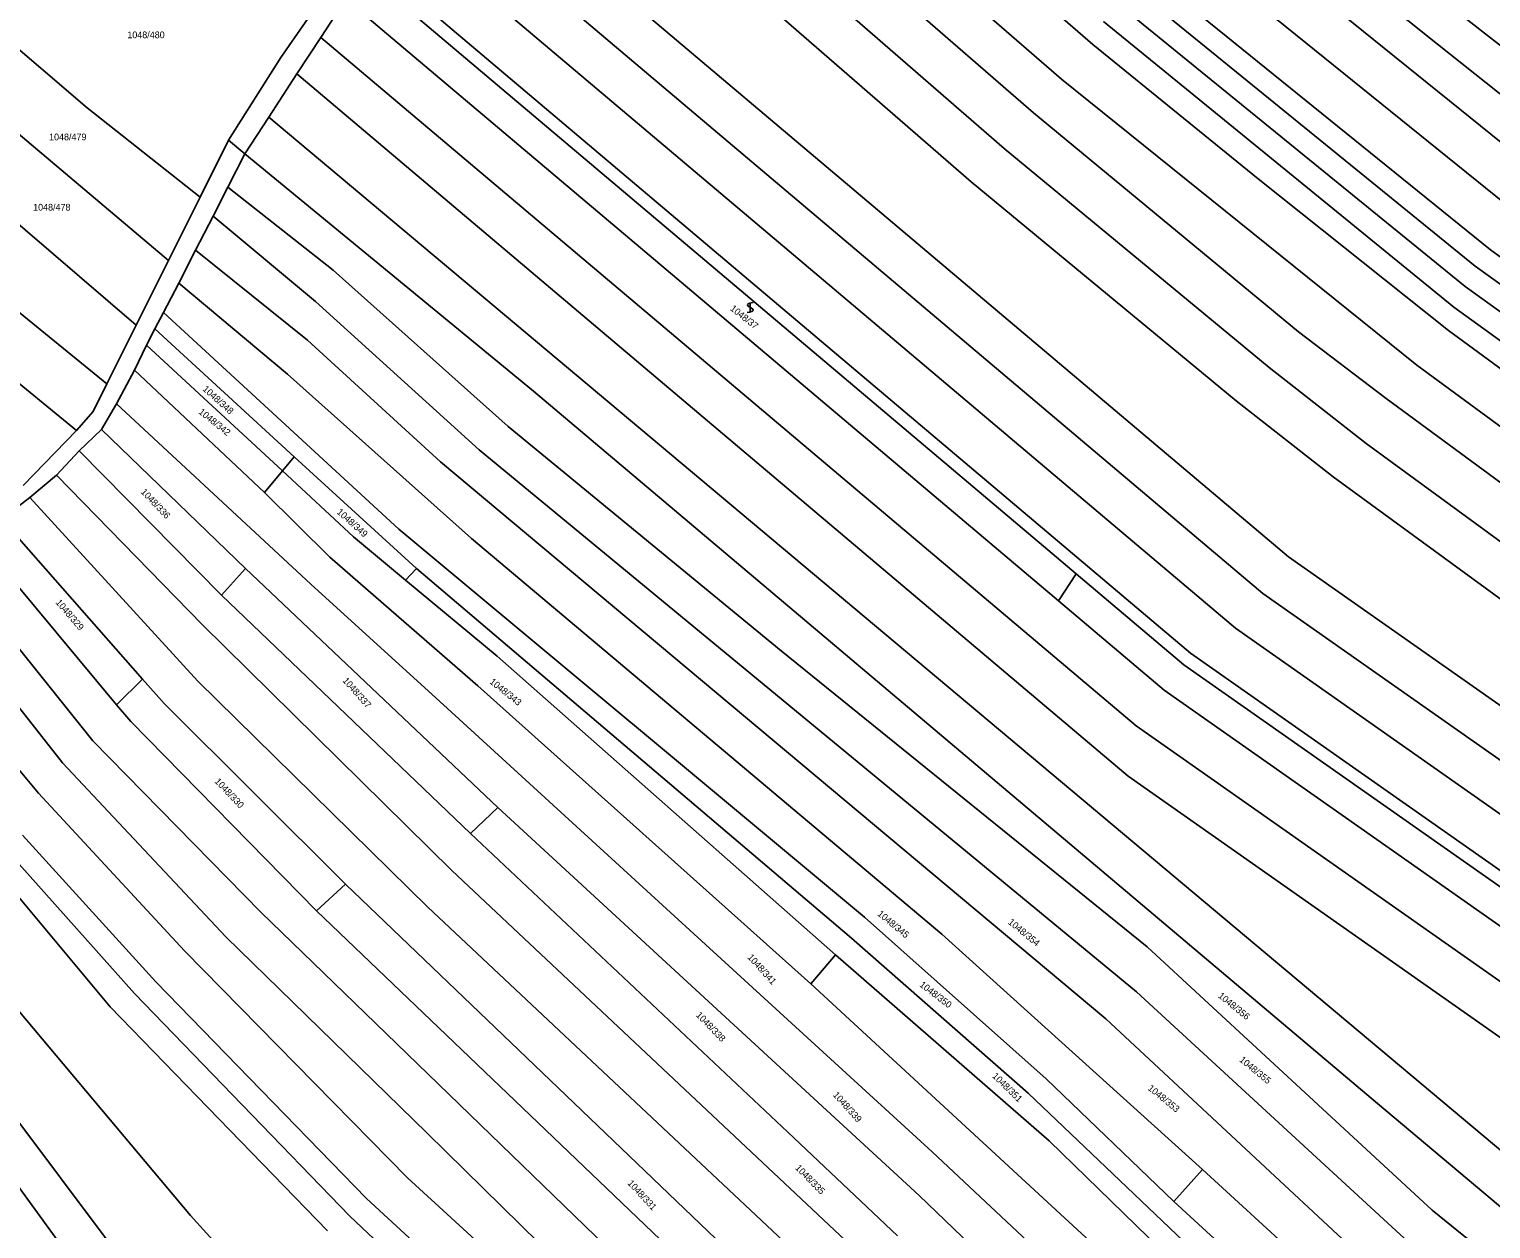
# Model space of a CAD drawing. Extents: x -580630 to -576196, y -1189024 to -1183567.
# Drawn here: x -577874.8 to -577503.7, y -1186079.1 to -1185774.5 of the extents above; entities that cross this region are included whole.
import ezdxf

# ---------------------------------------------------------------- set-up
doc = ezdxf.new("R2010")
doc.units = 0
for name, color, linetype in [('Vrstva 1', 7, 'Continuous'), ('Vrstva 18', 7, 'Continuous'), ('Vrstva 25', 7, 'Continuous'), ('Vrstva 6', 7, 'Continuous')]:
    doc.layers.add(name, color=color, linetype=linetype)

msp = doc.modelspace()

# ---------------------------------------------------------------- linework, layer by layer
at = {"layer": 'Vrstva 1'}
for p, q in [((-577664.3, -1185651.28), (-577332.73, -1185910.23)), ((-577732.43, -1185697.77), (-577619.85, -1185795.71)), ((-577627.3, -1185804.73), (-577740.7, -1185706.11)), ((-577749.09, -1185714.58), (-577635.66, -1185813.22)), ((-577677.91, -1185714.69), (-577604.76, -1185778.38)), ((-577612.74, -1185787.19), (-577685.89, -1185723.49)), ((-577662.14, -1185818.03), (-577765.26, -1185730.91)), ((-577773.22, -1185738.94), (-577670.09, -1185826.06)), ((-577578.38, -1185740.84), (-577487.79, -1185814.01)), ((-577781.14, -1185746.94), (-577678.01, -1185834.06)), ((-577494.62, -1185823.18), (-577585.21, -1185750.01)), ((-577551.27, -1185751.07), (-577517.23, -1185778.28)), ((-577683.41, -1185845.46), (-577786.54, -1185758.34)), ((-577704.33, -1185832.19), (-577788.36, -1185761.2)), ((-577507.7, -1185834.65), (-577596.7, -1185762.21)), ((-577503.8, -1185830.52), (-577591.91, -1185759.17)), ((-577800.75, -1185776.53), (-577794.39, -1185766.77)), ((-577794.39, -1185766.77), (-577710.36, -1185837.76)), ((-577599.25, -1185767.38), (-577510.25, -1185839.82)), ((-577810.89, -1185781.66), (-577802.62, -1185769.68)), ((-577513.13, -1185845.04), (-577602.04, -1185772.49)), ((-577806.8, -1185785.82), (-577800.75, -1185776.53)), ((-577697.62, -1185863.65), (-577800.75, -1185776.53)), ((-577604.76, -1185778.38), (-577562.76, -1185812.47)), ((-577517.23, -1185778.28), (-577477.78, -1185809.68)), ((-577824.19, -1185802.68), (-577810.89, -1185781.66)), ((-577813.91, -1185796.76), (-577806.8, -1185785.82)), ((-577806.8, -1185785.82), (-577703.68, -1185872.95)), ((-577522.47, -1185859.77), (-577612.74, -1185787.19)), ((-577820.01, -1185806.11), (-577813.91, -1185796.76)), ((-577699.01, -1185893.18), (-577813.91, -1185796.76)), ((-577619.85, -1185795.71), (-577552.56, -1185851.31)), ((-577831.37, -1185817.08), (-577824.19, -1185802.68)), ((-577820.01, -1185806.11), (-577824.19, -1185802.68)), ((-577824.35, -1185814.6), (-577820.01, -1185806.11)), ((-577820.01, -1185806.11), (-577746.74, -1185866.34)), ((-577559.97, -1185860.36), (-577627.3, -1185804.73)), ((-577635.66, -1185813.22), (-577568.33, -1185868.86)), ((-577562.76, -1185812.47), (-577514.49, -1185850.96)), ((-577839.43, -1185833.23), (-577831.37, -1185817.08)), ((-577828.11, -1185821.96), (-577824.35, -1185814.6)), ((-577555.11, -1185908.44), (-577662.14, -1185818.03)), ((-577832.52, -1185830.58), (-577828.11, -1185821.96)), ((-577670.09, -1185826.06), (-577561.55, -1185917.75)), ((-577836.81, -1185838.97), (-577832.52, -1185830.58)), ((-577616.14, -1185906.69), (-577704.33, -1185832.19)), ((-577412.08, -1185897.16), (-577503.8, -1185830.52)), ((-577847.6, -1185849.62), (-577839.43, -1185833.23)), ((-577678.01, -1185834.06), (-577568.51, -1185926.57)), ((-577415.03, -1185901.48), (-577507.7, -1185834.65)), ((-577840.66, -1185846.38), (-577836.81, -1185838.97)), ((-577710.36, -1185837.76), (-577613.45, -1185919.63)), ((-577510.25, -1185839.82), (-577417.58, -1185906.64)), ((-577842.84, -1185850.56), (-577840.66, -1185846.38)), ((-577579.93, -1185932.89), (-577683.41, -1185845.46)), ((-577420.56, -1185911.96), (-577513.13, -1185845.04)), ((-577855.03, -1185864.52), (-577847.6, -1185849.62)), ((-577845, -1185854.71), (-577842.84, -1185850.56)), ((-577514.49, -1185850.96), (-577440.82, -1185905.19)), ((-577848, -1185861.04), (-577845, -1185854.71)), ((-577552.56, -1185851.31), (-577530.26, -1185868.26)), ((-577852.6, -1185869.56), (-577848, -1185861.04)), ((-577535.34, -1185879.64), (-577559.97, -1185860.36)), ((-577448.81, -1185913.99), (-577522.47, -1185859.77)), ((-577858.52, -1185871.5), (-577855.03, -1185864.52)), ((-577593.78, -1185951.38), (-577697.62, -1185863.65)), ((-577856.45, -1185876.12), (-577852.6, -1185869.56)), ((-577746.74, -1185866.34), (-577532.48, -1186047.27)), ((-577568.33, -1185868.86), (-577543.7, -1185888.14)), ((-577530.26, -1185868.26), (-577456.78, -1185922.41)), ((-577862.79, -1185876.35), (-577858.52, -1185871.5)), ((-577703.68, -1185872.95), (-577595.78, -1185964.13)), ((-577876.32, -1185890.37), (-577862.79, -1185876.35)), ((-577856.45, -1185876.12), (-577862.11, -1185881.51)), ((-577462.45, -1185933.01), (-577535.34, -1185879.64)), ((-577867.84, -1185887.69), (-577862.11, -1185881.51)), ((-577874.61, -1185893.34), (-577867.84, -1185887.69)), ((-577543.7, -1185888.14), (-577470.8, -1185941.51)), ((-577881.68, -1185898.84), (-577874.61, -1185893.34)), ((-577584.11, -1185989.6), (-577699.01, -1185893.18)), ((-577609, -1185912.72), (-577616.14, -1185906.69)), ((-577410.98, -1186009.73), (-577555.11, -1185908.44)), ((-577613.45, -1185919.63), (-577609, -1185912.72)), ((-577581.64, -1185935.83), (-577609, -1185912.72)), ((-577561.55, -1185917.75), (-577417.41, -1186019.03)), ((-577613.45, -1185919.63), (-577586.61, -1185942.3)), ((-577568.51, -1185926.57), (-577424.38, -1186027.85)), ((-577437.5, -1186037.11), (-577581.64, -1185935.83)), ((-577435.79, -1186034.17), (-577579.93, -1185932.89)), ((-577586.61, -1185942.3), (-577442.47, -1186043.59)), ((-577449.64, -1186052.66), (-577593.78, -1185951.38)), ((-577595.78, -1185964.13), (-577451.64, -1186065.41)), ((-577474.77, -1186081.35), (-577584.11, -1185989.6)), ((-577532.48, -1186047.27), (-577480.98, -1186090.61))]:
    msp.add_line(p, q, dxfattribs=at)
at = {"layer": 'Vrstva 25'}
for points in [[(-577690.97, -1185843.89), (-577691.48, -1185843.95), (-577691.83, -1185844), (-577692.07, -1185844.08), (-577692.25, -1185844.19), (-577692.37, -1185844.28), (-577692.42, -1185844.45), (-577692.37, -1185844.68), (-577691.98, -1185845), (-577691.42, -1185845.31), (-577691.07, -1185845.58), (-577691, -1185845.78), (-577691.07, -1185845.98), (-577691.23, -1185846.11), (-577691.42, -1185846.18), (-577691.95, -1185846.31), (-577692.47, -1185846.38)], [(-577691.72, -1185846.39), (-577691.72, -1185845.12), (-577691.72, -1185843.89)]]:
    msp.add_lwpolyline(points, dxfattribs=at)
at = {"layer": 'Vrstva 6'}
for p, q in [((-577860.05, -1185794.41), (-577894.53, -1185764.98)), ((-577839.43, -1185833.23), (-577908.46, -1185774.88)), ((-577923.11, -1185784.8), (-577847.6, -1185849.62)), ((-577831.37, -1185817.08), (-577860.05, -1185794.41)), ((-577855.03, -1185864.52), (-577939.34, -1185795.85)), ((-577950.99, -1185804.05), (-577862.79, -1185876.35)), ((-577824.35, -1185814.6), (-577797.61, -1185835.65)), ((-577828.11, -1185821.96), (-577802.12, -1185843.61)), ((-577832.52, -1185830.58), (-577804.09, -1185853.45)), ((-577797.61, -1185835.65), (-577753.15, -1185875.32)), ((-577836.81, -1185838.97), (-577809.2, -1185862.03)), ((-577802.12, -1185843.61), (-577760.54, -1185881.29)), ((-577840.66, -1185846.38), (-577780.96, -1185901.39)), ((-577842.84, -1185850.56), (-577807.49, -1185883.08)), ((-577845, -1185854.71), (-577810.5, -1185886.6)), ((-577770.34, -1185884.35), (-577804.09, -1185853.45)), ((-577848, -1185861.04), (-577815.01, -1185892.1)), ((-577809.2, -1185862.03), (-577762.5, -1185903.79)), ((-577852.6, -1185869.56), (-577803.27, -1185915.37)), ((-577819.9, -1185911.43), (-577856.45, -1185876.12)), ((-577753.15, -1185875.32), (-577683.86, -1185932.3)), ((-577862.11, -1185881.51), (-577825.92, -1185918.14)), ((-577810.5, -1185886.6), (-577807.49, -1185883.08)), ((-577776.46, -1185911.38), (-577807.49, -1185883.08)), ((-577770.34, -1185884.35), (-577601.46, -1186025.8)), ((-577760.54, -1185881.29), (-577593.69, -1186018.87)), ((-577867.84, -1185887.69), (-577830.78, -1185925.68)), ((-577815.01, -1185892.1), (-577810.5, -1185886.6)), ((-577810.5, -1185886.6), (-577792.42, -1185903.4)), ((-577874.61, -1185893.34), (-577831.99, -1185940)), ((-577815.01, -1185892.1), (-577798.43, -1185908.53)), ((-577881.68, -1185898.84), (-577845.97, -1185939.54)), ((-577780.96, -1185901.39), (-577662.69, -1185999.97)), ((-577852.61, -1185946.01), (-577888.01, -1185903.5)), ((-577792.42, -1185903.4), (-577779.23, -1185914.36)), ((-577762.5, -1185903.79), (-577643.08, -1186004.26)), ((-577895.32, -1185909.32), (-577858.63, -1185955.13)), ((-577798.43, -1185908.53), (-577760.92, -1185941.24)), ((-577825.92, -1185918.14), (-577819.9, -1185911.43)), ((-577755.8, -1185972.07), (-577819.9, -1185911.43)), ((-577779.23, -1185914.36), (-577776.46, -1185911.38)), ((-577666.02, -1186005.31), (-577776.46, -1185911.38)), ((-577902.14, -1185915.36), (-577866.29, -1185960.73)), ((-577803.27, -1185915.37), (-577771.5, -1185944.23)), ((-577779.23, -1185914.36), (-577755.96, -1185933.7)), ((-577825.92, -1185918.14), (-577762.73, -1185978.7)), ((-577910.1, -1185923.35), (-577872.43, -1185968.42)), ((-577830.78, -1185925.68), (-577767.51, -1185988.09)), ((-577683.86, -1185932.3), (-577590.92, -1186007.5)), ((-577755.96, -1185933.7), (-577670.09, -1186009.52)), ((-577852.61, -1185946.01), (-577845.97, -1185939.54)), ((-577845.97, -1185939.54), (-577840.55, -1185945.72)), ((-577831.99, -1185940), (-577773.54, -1185997.43)), ((-577760.92, -1185941.24), (-577676.34, -1186016.85)), ((-577849, -1185950.23), (-577852.61, -1185946.01)), ((-577840.55, -1185945.72), (-577794.45, -1185991.55)), ((-577771.5, -1185944.23), (-577645.56, -1186059.56)), ((-577801.84, -1185998.32), (-577849, -1185950.23)), ((-577858.63, -1185955.13), (-577816, -1185998.7)), ((-577866.29, -1185960.73), (-577824.85, -1186004.91)), ((-577872.43, -1185968.42), (-577835.38, -1186008.52)), ((-577762.73, -1185978.7), (-577755.8, -1185972.07)), ((-577755.8, -1185972.07), (-577648.85, -1186070.58)), ((-577876.51, -1185979.11), (-577842.61, -1186016.34)), ((-577762.73, -1185978.7), (-577682.2, -1186054.57)), ((-577880.11, -1185983.34), (-577848.03, -1186019.36)), ((-577885.24, -1185985.52), (-577854.19, -1186022.75)), ((-577767.51, -1185988.09), (-577657.54, -1186091.42)), ((-577794.45, -1185991.55), (-577801.84, -1185998.32)), ((-577794.45, -1185991.55), (-577663.38, -1186117.12)), ((-577833.85, -1186075.71), (-577901.2, -1185995.5)), ((-577816, -1185998.7), (-577725.76, -1186085.99)), ((-577686.75, -1186108.38), (-577801.84, -1185998.32)), ((-577773.54, -1185997.43), (-577664.46, -1186099.81)), ((-577662.69, -1185999.97), (-577616.6, -1186040.97)), ((-577824.85, -1186004.91), (-577773.78, -1186054.8)), ((-577621.14, -1186044.67), (-577666.02, -1186005.31)), ((-577643.08, -1186004.26), (-577576.91, -1186064.03)), ((-577835.38, -1186008.52), (-577778.73, -1186066.11)), ((-577670.09, -1186009.52), (-577676.34, -1186016.85)), ((-577670.09, -1186009.52), (-577615.86, -1186056.7)), ((-577590.92, -1186007.5), (-577518.59, -1186074.31)), ((-577842.61, -1186016.34), (-577789.14, -1186071.36)), ((-577676.34, -1186016.85), (-577534.2, -1186147.99)), ((-577848.03, -1186019.36), (-577793.34, -1186075.89)), ((-577593.69, -1186018.87), (-577519.06, -1186087.55)), ((-577854.19, -1186022.75), (-577799.05, -1186079.58)), ((-577601.46, -1186025.8), (-577525.83, -1186096.16)), ((-577898.45, -1186039.68), (-577859.16, -1186093.53)), ((-577847.81, -1186091.45), (-577883.6, -1186043.78)), ((-577584.21, -1186072.18), (-577616.6, -1186040.97)), ((-577558.77, -1186104.07), (-577621.14, -1186044.67)), ((-577773.78, -1186054.8), (-577615.6, -1186209.77)), ((-577682.2, -1186054.57), (-577654.35, -1186080.86)), ((-577615.86, -1186056.7), (-577563.58, -1186107.51)), ((-577645.56, -1186059.56), (-577544.3, -1186154.15)), ((-577778.73, -1186066.11), (-577739.11, -1186102.44)), ((-577584.21, -1186072.18), (-577576.91, -1186064.03)), ((-577576.91, -1186064.03), (-577529.31, -1186107.59)), ((-577789.14, -1186071.36), (-577740.92, -1186115.71)), ((-577648.85, -1186070.58), (-577590.84, -1186126.36)), ((-577536.31, -1186115.98), (-577584.21, -1186072.18)), ((-577819.38, -1186091.56), (-577833.85, -1186075.71)), ((-577793.34, -1186075.89), (-577712.43, -1186151.86)), ((-577518.59, -1186074.31), (-577479.74, -1186105.8))]:
    msp.add_line(p, q, dxfattribs=at)

# ---------------------------------------------------------------- texts
at = {"layer": 'Vrstva 18'}
for s, p in [('1048/480', (-577849.86, -1185776.75)), ('1048/479', (-577869.726, -1185802.67)), ('1048/478', (-577873.776, -1185820.52))]:
    msp.add_text(s, height=1.7, dxfattribs=at).set_placement(p)
for s, rotation, p in [('1048/37', 321.48662, (-577696.971, -1185845.658)), ('1048/348', 317.93428, (-577830.875, -1185866.04)), ('1048/342', 321.20014, (-577831.913, -1185871.907)), ('1048/336', 313.75169, (-577846.581, -1185892.093)), ('1048/349', 318.04887, (-577796.817, -1185897.271)), ('1048/329', 310.71501, (-577868.181, -1185920.112)), ('1048/337', 311.63174, (-577795.338, -1185939.958)), ('1048/343', 321.14284, (-577758.04, -1185940.424)), ('1048/330', 313.40791, (-577827.826, -1185965.572)), ('1048/345', 320.45529, (-577659.578, -1185999.36)), ('1048/354', 320.74178, (-577626.415, -1186001.48)), ('1048/341', 312.2047, (-577692.552, -1186010.227)), ('1048/350', 322.40335, (-577648.893, -1186017.375)), ('1048/356', 320.74178, (-577573.085, -1186020.17)), ('1048/338', 314.03817, (-577705.634, -1186024.938)), ('1048/355', 320.74178, (-577567.701, -1186036.431)), ('1048/351', 315.81434, (-577630.43, -1186040.46)), ('1048/353', 320.74178, (-577590.932, -1186043.635)), ('1048/339', 312.2047, (-577670.855, -1186045.184)), ('1048/335', 314.55383, (-577680.438, -1186063.742)), ('1048/331', 312.77766, (-577722.998, -1186067.606))]:
    msp.add_text(s, height=1.7, rotation=rotation, dxfattribs=at).set_placement(p)

doc.saveas('drawing.dxf')
